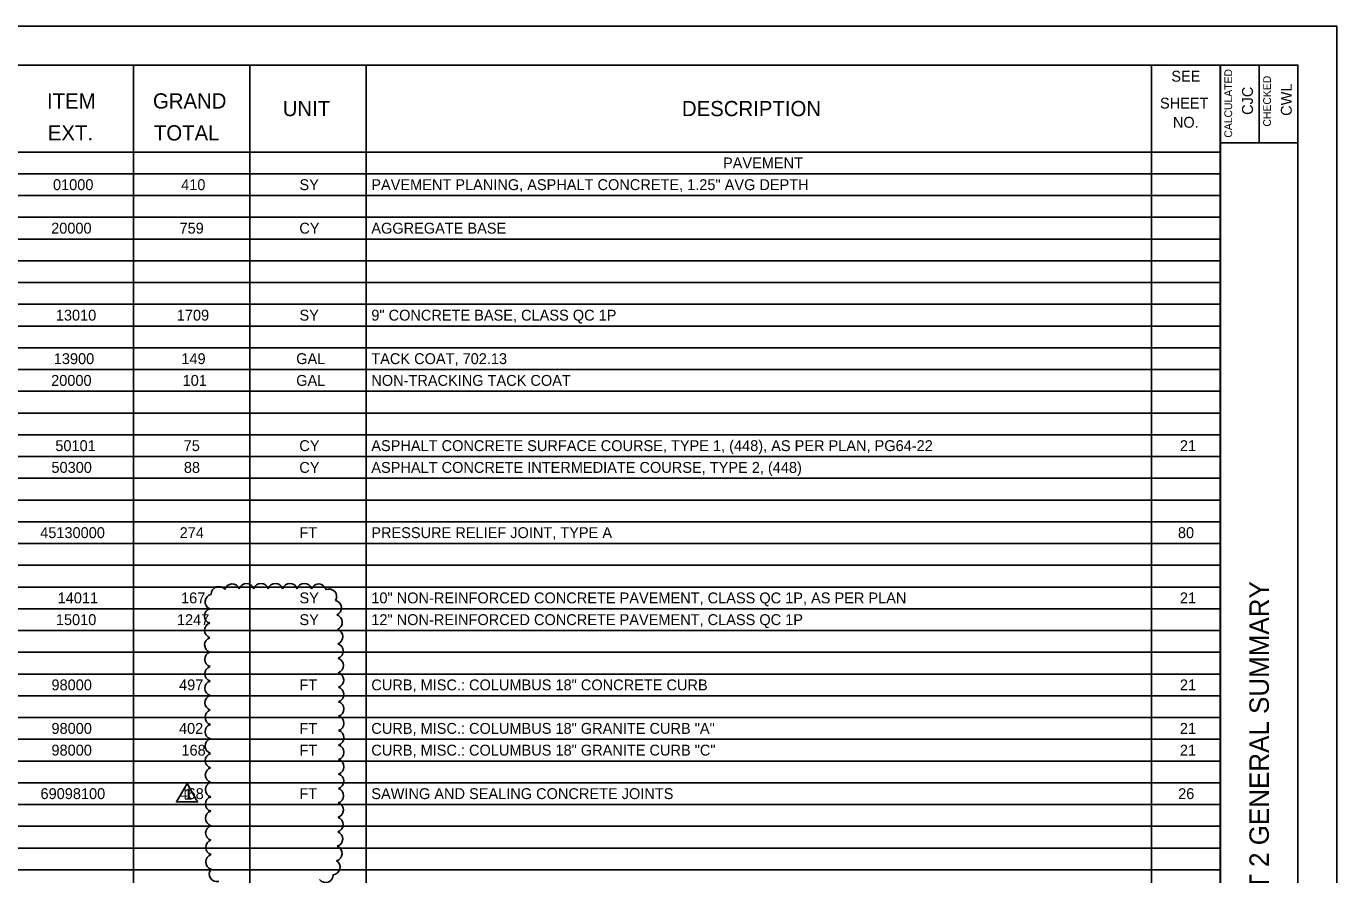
# Model space of a CAD drawing. Extents: x 0 to 34, y 0 to 22.
# Drawn here: x 17.12 to 34, y 11.08 to 22 of the extents above; entities that cross this region are included whole.
import ezdxf

# ---------------------------------------------------------------- set-up
doc = ezdxf.new("R2010")
doc.units = 0
for name, color, linetype in [('SH_Border', 7, 'Continuous'), ('SH_Cut_Line', 7, 'Continuous'), ('SH_Data', 7, 'Continuous'), ('SH_Text', 7, 'Continuous'), ('TX_P_1000', 7, 'Continuous')]:
    doc.layers.add(name, color=color, linetype=linetype)

msp = doc.modelspace()

# ---------------------------------------------------------------- linework, layer by layer
at = {"layer": 'SH_Border'}
for p, q in [((32.5, 0.5), (32.5, 21.5)), ((33, 21.5), (33, 20.5)), ((32.5, 20.5), (33.5, 20.5))]:
    msp.add_line(p, q, dxfattribs=at)
msp.add_lwpolyline([(2, 21.5), (33.5, 21.5), (33.5, 0.5), (2, 0.5)], close=True, dxfattribs=at)
at = {"layer": 'SH_Cut_Line'}
msp.add_lwpolyline([(0, 0), (34, 0), (34, 22), (0, 22)], close=True, dxfattribs=at)
at = {"layer": 'SH_Data'}
for p, q in [((15.72, 21.5), (32.504, 21.5)), ((18.504, 21.5), (18.504, 0.5)), ((20.002, 21.5), (20.002, 0.5)), ((21.501, 21.5), (21.501, 0.5)), ((31.614, 21.5), (31.614, 0.5)), ((32.504, 21.5), (32.504, 0.5)), ((2, 20.38), (32.504, 20.38)), ((2, 20.1), (32.504, 20.1)), ((2, 19.82), (32.504, 19.82)), ((2, 19.54), (32.504, 19.54)), ((2, 19.26), (32.504, 19.26)), ((2, 18.98), (32.504, 18.98)), ((2, 18.7), (32.504, 18.7)), ((2, 18.42), (32.504, 18.42)), ((2, 18.14), (32.504, 18.14)), ((2, 17.86), (32.504, 17.86)), ((2, 17.58), (32.504, 17.58)), ((2, 17.3), (32.504, 17.3)), ((2, 17.02), (32.504, 17.02)), ((2, 16.74), (32.504, 16.74)), ((2, 16.46), (32.504, 16.46)), ((2, 16.18), (32.504, 16.18)), ((2, 15.9), (32.504, 15.9)), ((2, 15.62), (32.504, 15.62)), ((2, 15.34), (32.504, 15.34)), ((2, 15.06), (32.504, 15.06)), ((2, 14.78), (32.504, 14.78)), ((2, 14.5), (32.504, 14.5)), ((2, 14.22), (32.504, 14.22)), ((2, 13.94), (32.504, 13.94)), ((2, 13.66), (32.504, 13.66)), ((2, 13.38), (32.504, 13.38)), ((2, 13.1), (32.504, 13.1)), ((2, 12.82), (32.504, 12.82)), ((2, 12.54), (32.504, 12.54)), ((2, 12.26), (32.504, 12.26)), ((2, 11.98), (32.504, 11.98)), ((2, 11.7), (32.504, 11.7)), ((2, 11.42), (32.504, 11.42)), ((2, 11.14), (32.504, 11.14))]:
    msp.add_line(p, q, dxfattribs=at)
at = {"layer": 'TX_P_1000'}
msp.add_lwpolyline([(19.194, 12.249), (19.057, 12.013), (19.33, 12.013)], close=True, dxfattribs=at)
for centre, radius, start, end in [((19.524, 14.59), 0.0975, 101.8161, 246.8161), ((19.602, 14.689), 0.0977, 36.7231, 181.7231), ((19.775, 14.722), 0.0976, 20.0252, 165.0252), ((19.96, 14.727), 0.0976, 18.0955, 163.0955), ((20.146, 14.728), 0.0976, 17.5007, 162.5007), ((20.332, 14.728), 0.0976, 17.5, 162.5), ((20.518, 14.728), 0.0976, 17.5, 162.5), ((20.704, 14.728), 0.0976, 17.4886, 162.4886), ((20.889, 14.722), 0.0976, 14.207, 159.207), ((21.023, 14.657), 0.0975, 328.8806, 113.8806), ((21.085, 14.512), 0.0976, 292.072, 77.072), ((19.516, 14.408), 0.0976, 107.7774, 252.7774), ((21.096, 14.327), 0.0976, 290.1112, 75.1112), ((19.517, 14.221), 0.0976, 107.7971, 252.7971), ((21.103, 14.141), 0.0976, 289.2389, 74.2389), ((19.518, 14.035), 0.0976, 107.805, 252.805), ((21.108, 13.955), 0.0976, 288.7142, 73.7142), ((19.519, 13.849), 0.0976, 107.8096, 252.8096), ((21.111, 13.769), 0.0976, 288.3537, 73.3537), ((19.52, 13.663), 0.0976, 107.8127, 252.8127), ((21.114, 13.583), 0.0976, 288.0863, 73.0863), ((19.521, 13.477), 0.0976, 107.815, 252.815), ((19.522, 13.29), 0.0976, 107.8168, 252.8168), ((21.115, 13.397), 0.0976, 287.8778, 72.8778), ((19.523, 13.104), 0.0976, 107.8182, 252.8182), ((21.116, 13.211), 0.0976, 287.7092, 72.7092), ((19.524, 12.918), 0.0976, 107.8194, 252.8194), ((21.117, 13.025), 0.0976, 287.5693, 72.5693), ((21.117, 12.839), 0.0976, 287.4584, 72.4584), ((19.525, 12.732), 0.0976, 107.8202, 252.8202), ((21.116, 12.653), 0.0976, 287.3535, 72.3535), ((19.526, 12.545), 0.0976, 107.8202, 252.8202), ((21.116, 12.466), 0.0976, 287.2279, 72.2279), ((19.527, 12.359), 0.0976, 107.8202, 252.8202), ((21.115, 12.28), 0.0976, 287.0737, 72.0737), ((19.528, 12.173), 0.0976, 107.8202, 252.8202), ((21.113, 12.094), 0.0976, 286.8782, 71.8782), ((19.529, 11.987), 0.0976, 107.8202, 252.8202), ((21.11, 11.908), 0.0976, 286.6187, 71.6187), ((19.53, 11.801), 0.0976, 107.8202, 252.8202), ((21.107, 11.722), 0.0976, 286.2502, 71.2502), ((19.531, 11.614), 0.0976, 107.8202, 252.8202), ((19.532, 11.428), 0.0976, 107.8202, 252.8202), ((21.102, 11.536), 0.0976, 285.6646, 70.6646), ((19.533, 11.242), 0.0976, 107.8202, 252.8202), ((21.094, 11.351), 0.0976, 284.493, 69.493), ((19.578, 11.085), 0.0976, 139.2641, 284.2641), ((21.068, 11.173), 0.0976, 273.9501, 58.9501), ((20.977, 11.072), 0.0977, 217.3339, 2.3339)]:
    msp.add_arc(centre, radius, start, end, dxfattribs=at)

# ---------------------------------------------------------------- texts
at = {"layer": 'SH_Data'}
for s, height, p in [('CALCULATED', 0.1, (32.652, 20.565)), ('CHECKED', 0.1, (33.152, 20.708)), ('CJC', 0.14, (32.92, 20.858)), ('CWL', 0.14, (33.42, 20.846)), ('4H PART 2 GENERAL SUMMARY', 0.25, (33.125, 9.672))]:
    msp.add_text(s, height=height, rotation=90, dxfattribs=at).set_placement(p)
at = {"layer": 'SH_Text'}
for s, height, p in [('SEE', 0.14, (31.869, 21.286)), ('ITEM', 0.196, (17.391, 20.94)), ('GRAND', 0.196, (18.755, 20.94)), ('UNIT', 0.196, (20.426, 20.842)), ('DESCRIPTION', 0.196, (25.567, 20.842)), ('SHEET', 0.14, (31.723, 20.94)), ('NO.', 0.14, (31.889, 20.693)), ('EXT.', 0.196, (17.401, 20.529)), ('TOTAL', 0.196, (18.767, 20.529)), ('PAVEMENT', 0.14, (26.096, 20.17)), ('01000', 0.14, (17.468, 19.89)), ('410', 0.14, (19.118, 19.89)), ('SY', 0.14, (20.642, 19.89)), ('PAVEMENT PLANING, ASPHALT CONCRETE, 1.25" AVG DEPTH', 0.14, (21.567, 19.89)), ('20000', 0.14, (17.444, 19.33)), ('759', 0.14, (19.097, 19.33)), ('CY', 0.14, (20.64, 19.33)), ('AGGREGATE BASE', 0.14, (21.567, 19.33)), ('13010', 0.14, (17.504, 18.21)), ('1709', 0.14, (19.062, 18.21)), ('SY', 0.14, (20.642, 18.21)), ('9" CONCRETE BASE, CLASS QC 1P', 0.14, (21.567, 18.21)), ('13900', 0.14, (17.478, 17.65)), ('149', 0.14, (19.121, 17.65)), ('GAL', 0.14, (20.6, 17.65)), ('TACK COAT, 702.13', 0.14, (21.567, 17.65)), ('20000', 0.14, (17.444, 17.37)), ('101', 0.14, (19.137, 17.37)), ('GAL', 0.14, (20.6, 17.37)), ('NON-TRACKING TACK COAT', 0.14, (21.567, 17.37)), ('50101', 0.14, (17.498, 16.53)), ('75', 0.14, (19.151, 16.53)), ('CY', 0.14, (20.64, 16.53)), ('ASPHALT CONCRETE SURFACE COURSE, TYPE 1, (448), AS PER PLAN, PG64-22', 0.14, (21.567, 16.53)), ('21', 0.14, (31.979, 16.53)), ('50300', 0.14, (17.448, 16.25)), ('88', 0.14, (19.153, 16.25)), ('CY', 0.14, (20.64, 16.25)), ('ASPHALT CONCRETE INTERMEDIATE COURSE, TYPE 2, (448)', 0.14, (21.567, 16.25)), ('45130000', 0.14, (17.303, 15.41)), ('274', 0.14, (19.099, 15.41)), ('FT', 0.14, (20.642, 15.41)), ('PRESSURE RELIEF JOINT, TYPE A', 0.14, (21.567, 15.41)), ('80', 0.14, (31.954, 15.41)), ('14011', 0.14, (17.528, 14.57)), ('167', 0.14, (19.117, 14.57)), ('SY', 0.14, (20.642, 14.57)), ('10" NON-REINFORCED CONCRETE PAVEMENT, CLASS QC 1P, AS PER PLAN', 0.14, (21.567, 14.57)), ('21', 0.14, (31.979, 14.57)), ('15010', 0.14, (17.505, 14.29)), ('1247', 0.14, (19.064, 14.29)), ('SY', 0.14, (20.642, 14.29)), ('12" NON-REINFORCED CONCRETE PAVEMENT, CLASS QC 1P', 0.14, (21.567, 14.29)), ('98000', 0.14, (17.448, 13.45)), ('497', 0.14, (19.091, 13.45)), ('FT', 0.14, (20.642, 13.45)), ('CURB, MISC.: COLUMBUS 18" CONCRETE CURB', 0.14, (21.567, 13.45)), ('21', 0.14, (31.979, 13.45)), ('98000', 0.14, (17.448, 12.89)), ('402', 0.14, (19.09, 12.89)), ('FT', 0.14, (20.642, 12.89)), ('CURB, MISC.: COLUMBUS 18" GRANITE CURB "A"', 0.14, (21.567, 12.89)), ('21', 0.14, (31.979, 12.89)), ('98000', 0.14, (17.448, 12.61)), ('168', 0.14, (19.122, 12.61)), ('FT', 0.14, (20.642, 12.61)), ('CURB, MISC.: COLUMBUS 18" GRANITE CURB "C"', 0.14, (21.567, 12.61)), ('21', 0.14, (31.979, 12.61)), ('69098100', 0.14, (17.307, 12.05)), ('468', 0.14, (19.097, 12.05)), ('FT', 0.14, (20.642, 12.05)), ('SAWING AND SEALING CONCRETE JOINTS', 0.14, (21.567, 12.05)), ('26', 0.14, (31.957, 12.05))]:
    msp.add_text(s, height=height, dxfattribs=at).set_placement(p)
at = {"layer": 'TX_P_1000'}
msp.add_text('1', height=0.14, rotation=360, dxfattribs=at).set_placement((19.155, 12.043))

doc.saveas('drawing.dxf')
